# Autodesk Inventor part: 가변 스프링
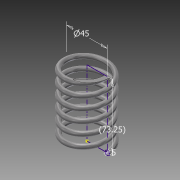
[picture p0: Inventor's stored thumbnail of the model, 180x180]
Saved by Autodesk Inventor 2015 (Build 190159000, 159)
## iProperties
Created: 2015-10
Part Number: 가변 스프링
Material: 강철, 연강
Document SubType Name: Modeling
Designer: youjin17
Mass: 129.004 g
Surface Area: 133.165 cm^2
Volume: 16.4336 cm^3
Density: 7.85 g/cm^3
Appearance: 반연마
Author: youjin17
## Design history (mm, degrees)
sketch "스케치1"
  geometry: L1 (0, 0)-(-22.5, 0); L2 (-22.5, 0)-(-22.5, 73.25); L3 (-22.5, 73.25)-(0, 73.25); L4 (0, 73.25)-(0, 0); C1 r 2.5 at (-22.5, 0); 1 further point
  constraints: 8 end point, 2 coincident, 2 parallel, 1 centre point, 1 horizontal, 1 perpendicular
  dimensions: "d0" = 73.25 distance of L1.end L2.end (derived); "d1" = 45 diameter of L2 L4; "d2" = 5 diameter of C1
feature "코일1" sketch "스케치1" pitch "d3" = 10; turns "d5" = 6; dims "d4" = 73.25 (= d0), "d6" = 0, angle "d7" = 90 deg, angle "d8" = 90 deg, "d9" = 0, "d10" = 0
sketch "스케치2"
  geometry: L1 (25, 0)-(20, 0) reference; 1 further point
  constraints: 1 horizontal alignment
extrude "돌출1" cut sketch "스케치2" stored distance "d11" = 10; taper "d12" = 0 deg
node "작업 평면1"
sketch "스케치3"
  geometry: L1 (-25, 0)-(-20, 0) reference; 1 further point
  constraints: 1 horizontal alignment
extrude "돌출2" cut sketch "스케치3" stored distance "d13" = 10; taper "d14" = 0 deg
node "솔리드1"
node "절단 모서리 투영1"
node "절단 모서리 투영2"
